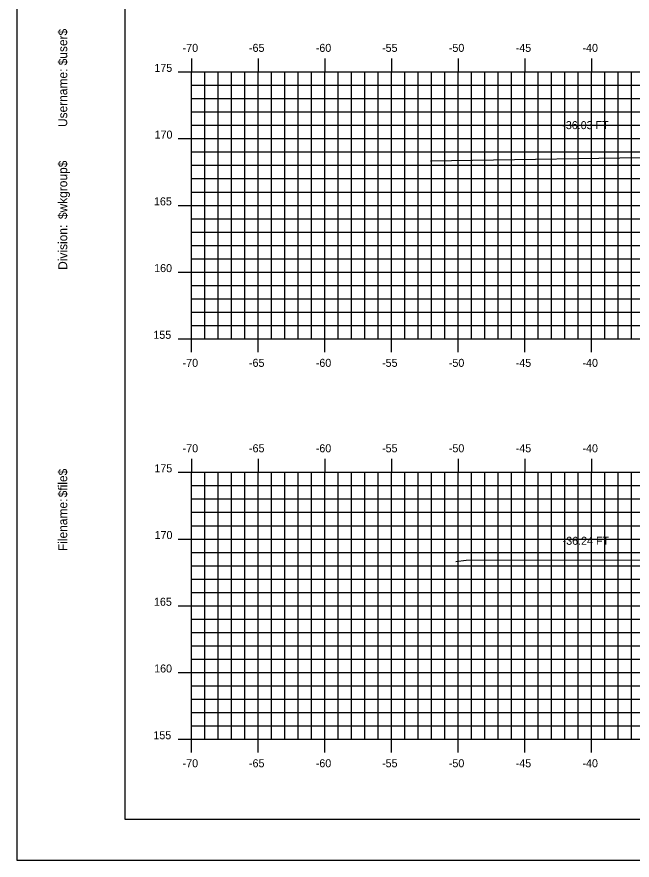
# Model space of a CAD drawing. Extents: x 1141868 to 1142038, y 608981 to 609091.
# Drawn here: x 1141867.7 to 1141913.8, y 608981.3 to 609044.5 of the extents above; entities that cross this region are included whole.
import ezdxf

# ---------------------------------------------------------------- set-up
doc = ezdxf.new("R2010")
doc.units = 0
for name, color, linetype in [('BORDER', 7, 'Continuous'), ('D_Text_Standard', 7, 'Continuous'), ('H_V ANNOTATION', 7, 'Continuous'), ('MAJOR', 7, 'Continuous'), ('MINOR', 7, 'Continuous'), ('PLOT BOUNDARY', 7, 'Continuous'), ('S_Roadway_Centerline', 7, 'Continuous')]:
    doc.layers.add(name, color=color, linetype=linetype)

msp = doc.modelspace()

# ---------------------------------------------------------------- linework, layer by layer
at = {"layer": 'BORDER'}
msp.add_lwpolyline([(1141875.784, 608984.335), (1142035.784, 608984.335), (1142035.784, 609089.335), (1141875.784, 609089.335)], close=True, dxfattribs=at)
at = {"layer": 'MAJOR'}
for p, q in [((1141880.784, 609041.337), (1141880.784, 609040.335)), ((1141885.784, 609041.337), (1141885.784, 609040.335)), ((1141890.784, 609041.337), (1141890.784, 609040.335)), ((1141895.784, 609041.337), (1141895.784, 609040.335)), ((1141900.784, 609041.337), (1141900.784, 609040.335)), ((1141905.784, 609041.337), (1141905.784, 609040.335)), ((1141910.784, 609041.337), (1141910.784, 609040.335)), ((1141879.782, 609040.335), (1141880.784, 609040.335)), ((1141880.784, 609040.335), (1142020.784, 609040.335)), ((1141880.784, 609020.335), (1141880.784, 609040.335)), ((1141880.784, 609020.335), (1141880.784, 609040.335)), ((1141880.784, 609040.335), (1142020.784, 609040.335)), ((1141885.784, 609020.335), (1141885.784, 609040.335)), ((1141890.784, 609020.335), (1141890.784, 609040.335)), ((1141895.784, 609020.335), (1141895.784, 609040.335)), ((1141900.784, 609020.335), (1141900.784, 609040.335)), ((1141905.784, 609020.335), (1141905.784, 609040.335)), ((1141910.784, 609020.335), (1141910.784, 609040.335)), ((1141879.782, 609035.335), (1141880.784, 609035.335)), ((1141880.784, 609035.335), (1142020.784, 609035.335)), ((1141879.782, 609030.335), (1141880.784, 609030.335)), ((1141880.784, 609030.335), (1142020.784, 609030.335)), ((1141879.782, 609025.335), (1141880.784, 609025.335)), ((1141880.784, 609025.335), (1142020.784, 609025.335)), ((1141879.782, 609020.335), (1141880.784, 609020.335)), ((1141880.784, 609020.335), (1142020.784, 609020.335)), ((1141880.784, 609020.335), (1142020.784, 609020.335)), ((1141880.784, 609019.333), (1141880.784, 609020.335)), ((1141885.784, 609019.333), (1141885.784, 609020.335)), ((1141890.784, 609019.333), (1141890.784, 609020.335)), ((1141895.784, 609019.333), (1141895.784, 609020.335)), ((1141900.784, 609019.333), (1141900.784, 609020.335)), ((1141905.784, 609019.333), (1141905.784, 609020.335)), ((1141910.784, 609019.333), (1141910.784, 609020.335)), ((1141880.784, 609011.337), (1141880.784, 609010.335)), ((1141885.784, 609011.337), (1141885.784, 609010.335)), ((1141890.784, 609011.337), (1141890.784, 609010.335)), ((1141895.784, 609011.337), (1141895.784, 609010.335)), ((1141900.784, 609011.337), (1141900.784, 609010.335)), ((1141905.784, 609011.337), (1141905.784, 609010.335)), ((1141910.784, 609011.337), (1141910.784, 609010.335)), ((1141879.782, 609010.335), (1141880.784, 609010.335)), ((1141880.784, 609010.335), (1142020.784, 609010.335)), ((1141880.784, 608990.335), (1141880.784, 609010.335)), ((1141880.784, 608990.335), (1141880.784, 609010.335)), ((1141880.784, 609010.335), (1142020.784, 609010.335)), ((1141885.784, 608990.335), (1141885.784, 609010.335)), ((1141890.784, 608990.335), (1141890.784, 609010.335)), ((1141895.784, 608990.335), (1141895.784, 609010.335)), ((1141900.784, 608990.335), (1141900.784, 609010.335)), ((1141905.784, 608990.335), (1141905.784, 609010.335)), ((1141910.784, 608990.335), (1141910.784, 609010.335)), ((1141879.782, 609005.335), (1141880.784, 609005.335)), ((1141880.784, 609005.335), (1142020.784, 609005.335)), ((1141879.782, 609000.335), (1141880.784, 609000.335)), ((1141880.784, 609000.335), (1142020.784, 609000.335)), ((1141879.782, 608995.335), (1141880.784, 608995.335)), ((1141880.784, 608995.335), (1142020.784, 608995.335)), ((1141879.782, 608990.335), (1141880.784, 608990.335)), ((1141880.784, 608990.335), (1142020.784, 608990.335)), ((1141880.784, 608990.335), (1142020.784, 608990.335)), ((1141880.784, 608989.333), (1141880.784, 608990.335)), ((1141885.784, 608989.333), (1141885.784, 608990.335)), ((1141890.784, 608989.333), (1141890.784, 608990.335)), ((1141895.784, 608989.333), (1141895.784, 608990.335)), ((1141900.784, 608989.333), (1141900.784, 608990.335)), ((1141905.784, 608989.333), (1141905.784, 608990.335)), ((1141910.784, 608989.333), (1141910.784, 608990.335))]:
    msp.add_line(p, q, dxfattribs=at)
at = {"layer": 'MINOR'}
for p, q in [((1141881.784, 609020.335), (1141881.784, 609040.335)), ((1141882.784, 609020.335), (1141882.784, 609040.335)), ((1141883.784, 609020.335), (1141883.784, 609040.335)), ((1141884.784, 609020.335), (1141884.784, 609040.335)), ((1141886.784, 609020.335), (1141886.784, 609040.335)), ((1141887.784, 609020.335), (1141887.784, 609040.335)), ((1141888.784, 609020.335), (1141888.784, 609040.335)), ((1141889.784, 609020.335), (1141889.784, 609040.335)), ((1141891.784, 609020.335), (1141891.784, 609040.335)), ((1141892.784, 609020.335), (1141892.784, 609040.335)), ((1141893.784, 609020.335), (1141893.784, 609040.335)), ((1141894.784, 609020.335), (1141894.784, 609040.335)), ((1141896.784, 609020.335), (1141896.784, 609040.335)), ((1141897.784, 609020.335), (1141897.784, 609040.335)), ((1141898.784, 609020.335), (1141898.784, 609040.335)), ((1141899.784, 609020.335), (1141899.784, 609040.335)), ((1141901.784, 609020.335), (1141901.784, 609040.335)), ((1141902.784, 609020.335), (1141902.784, 609040.335)), ((1141903.784, 609020.335), (1141903.784, 609040.335)), ((1141904.784, 609020.335), (1141904.784, 609040.335)), ((1141906.784, 609020.335), (1141906.784, 609040.335)), ((1141907.784, 609020.335), (1141907.784, 609040.335)), ((1141908.784, 609020.335), (1141908.784, 609040.335)), ((1141909.784, 609020.335), (1141909.784, 609040.335)), ((1141911.784, 609020.335), (1141911.784, 609040.335)), ((1141912.784, 609020.335), (1141912.784, 609040.335)), ((1141913.784, 609020.335), (1141913.784, 609040.335)), ((1141880.784, 609039.335), (1142020.784, 609039.335)), ((1141880.784, 609039.335), (1141881.786, 609039.335)), ((1141880.784, 609038.335), (1142020.784, 609038.335)), ((1141880.784, 609038.335), (1141881.786, 609038.335)), ((1141880.784, 609037.335), (1142020.784, 609037.335)), ((1141880.784, 609037.335), (1141881.786, 609037.335)), ((1141880.784, 609036.335), (1142020.784, 609036.335)), ((1141880.784, 609036.335), (1141881.786, 609036.335)), ((1141880.784, 609034.335), (1142020.784, 609034.335)), ((1141880.784, 609034.335), (1141881.786, 609034.335)), ((1141880.784, 609033.335), (1142020.784, 609033.335)), ((1141880.784, 609033.335), (1141881.786, 609033.335)), ((1141880.784, 609032.335), (1142020.784, 609032.335)), ((1141880.784, 609032.335), (1141881.786, 609032.335)), ((1141880.784, 609031.335), (1142020.784, 609031.335)), ((1141880.784, 609031.335), (1141881.786, 609031.335)), ((1141880.784, 609029.335), (1142020.784, 609029.335)), ((1141880.784, 609029.335), (1141881.786, 609029.335)), ((1141880.784, 609028.335), (1142020.784, 609028.335)), ((1141880.784, 609028.335), (1141881.786, 609028.335)), ((1141880.784, 609027.335), (1142020.784, 609027.335)), ((1141880.784, 609027.335), (1141881.786, 609027.335)), ((1141880.784, 609026.335), (1142020.784, 609026.335)), ((1141880.784, 609026.335), (1141881.786, 609026.335)), ((1141880.784, 609024.335), (1142020.784, 609024.335)), ((1141880.784, 609024.335), (1141881.786, 609024.335)), ((1141880.784, 609023.335), (1142020.784, 609023.335)), ((1141880.784, 609023.335), (1141881.786, 609023.335)), ((1141880.784, 609022.335), (1142020.784, 609022.335)), ((1141880.784, 609022.335), (1141881.786, 609022.335)), ((1141880.784, 609021.335), (1142020.784, 609021.335)), ((1141880.784, 609021.335), (1141881.786, 609021.335)), ((1141881.784, 608990.335), (1141881.784, 609010.335)), ((1141882.784, 608990.335), (1141882.784, 609010.335)), ((1141883.784, 608990.335), (1141883.784, 609010.335)), ((1141884.784, 608990.335), (1141884.784, 609010.335)), ((1141886.784, 608990.335), (1141886.784, 609010.335)), ((1141887.784, 608990.335), (1141887.784, 609010.335)), ((1141888.784, 608990.335), (1141888.784, 609010.335)), ((1141889.784, 608990.335), (1141889.784, 609010.335)), ((1141891.784, 608990.335), (1141891.784, 609010.335)), ((1141892.784, 608990.335), (1141892.784, 609010.335)), ((1141893.784, 608990.335), (1141893.784, 609010.335)), ((1141894.784, 608990.335), (1141894.784, 609010.335)), ((1141896.784, 608990.335), (1141896.784, 609010.335)), ((1141897.784, 608990.335), (1141897.784, 609010.335)), ((1141898.784, 608990.335), (1141898.784, 609010.335)), ((1141899.784, 608990.335), (1141899.784, 609010.335)), ((1141901.784, 608990.335), (1141901.784, 609010.335)), ((1141902.784, 608990.335), (1141902.784, 609010.335)), ((1141903.784, 608990.335), (1141903.784, 609010.335)), ((1141904.784, 608990.335), (1141904.784, 609010.335)), ((1141906.784, 608990.335), (1141906.784, 609010.335)), ((1141907.784, 608990.335), (1141907.784, 609010.335)), ((1141908.784, 608990.335), (1141908.784, 609010.335)), ((1141909.784, 608990.335), (1141909.784, 609010.335)), ((1141911.784, 608990.335), (1141911.784, 609010.335)), ((1141912.784, 608990.335), (1141912.784, 609010.335)), ((1141913.784, 608990.335), (1141913.784, 609010.335)), ((1141880.784, 609009.335), (1142020.784, 609009.335)), ((1141880.784, 609009.335), (1141881.786, 609009.335)), ((1141880.784, 609008.335), (1142020.784, 609008.335)), ((1141880.784, 609008.335), (1141881.786, 609008.335)), ((1141880.784, 609007.335), (1142020.784, 609007.335)), ((1141880.784, 609007.335), (1141881.786, 609007.335)), ((1141880.784, 609006.335), (1142020.784, 609006.335)), ((1141880.784, 609006.335), (1141881.786, 609006.335)), ((1141880.784, 609004.335), (1142020.784, 609004.335)), ((1141880.784, 609004.335), (1141881.786, 609004.335)), ((1141880.784, 609003.335), (1142020.784, 609003.335)), ((1141880.784, 609003.335), (1141881.786, 609003.335)), ((1141880.784, 609002.335), (1142020.784, 609002.335)), ((1141880.784, 609002.335), (1141881.786, 609002.335)), ((1141880.784, 609001.335), (1142020.784, 609001.335)), ((1141880.784, 609001.335), (1141881.786, 609001.335)), ((1141880.784, 608999.335), (1142020.784, 608999.335)), ((1141880.784, 608999.335), (1141881.786, 608999.335)), ((1141880.784, 608998.335), (1142020.784, 608998.335)), ((1141880.784, 608998.335), (1141881.786, 608998.335)), ((1141880.784, 608997.335), (1142020.784, 608997.335)), ((1141880.784, 608997.335), (1141881.786, 608997.335)), ((1141880.784, 608996.335), (1142020.784, 608996.335)), ((1141880.784, 608996.335), (1141881.786, 608996.335)), ((1141880.784, 608994.335), (1142020.784, 608994.335)), ((1141880.784, 608994.335), (1141881.786, 608994.335)), ((1141880.784, 608993.335), (1142020.784, 608993.335)), ((1141880.784, 608993.335), (1141881.786, 608993.335)), ((1141880.784, 608992.335), (1142020.784, 608992.335)), ((1141880.784, 608992.335), (1141881.786, 608992.335)), ((1141880.784, 608991.335), (1142020.784, 608991.335)), ((1141880.784, 608991.335), (1141881.786, 608991.335))]:
    msp.add_line(p, q, dxfattribs=at)
at = {"layer": 'PLOT BOUNDARY'}
msp.add_lwpolyline([(1141867.691, 608981.276), (1142037.691, 608981.276), (1142037.691, 609091.276), (1141867.691, 609091.276)], close=True, dxfattribs=at)
at = {"layer": 'S_Roadway_Centerline'}
for points in [[(1141898.714, 609033.675), (1141917.629, 609033.96), (1141928.482, 609033.842), (1141932.036, 609032.906), (1141933.204, 609032.648), (1141934.418, 609032.95), (1141936.171, 609033.793), (1141938.888, 609033.718), (1141940.258, 609033.785), (1141943.4, 609033.889), (1141951.951, 609034.107), (1141958.412, 609033.998), (1141962.656, 609033.973), (1141964.386, 609033.91), (1141966.817, 609033.803), (1141966.877, 609033.693), (1141968.111, 609033.369), (1141969.228, 609033.74), (1141970.594, 609033.351), (1141971.805, 609033.711), (1141975.428, 609033.517), (1141988.146, 609032.877), (1141997.951, 609033.132)], [(1141900.602, 609003.644), (1141901.394, 609003.749), (1141915.746, 609003.783), (1141928.977, 609003.95), (1141931.483, 609003.382), (1141934.466, 609002.656), (1141935.906, 609003.083), (1141937.139, 609003.558), (1141939.061, 609003.555), (1141941.092, 609003.71), (1141946.4, 609003.848), (1141952.444, 609004.051), (1141957.538, 609004.023), (1141963.377, 609003.905), (1141965.582, 609003.828), (1141967.5, 609003.599), (1141969.235, 609003.105), (1141970.695, 609002.835), (1141974.484, 609003.124), (1141975.978, 609003.567), (1141986.319, 609003.2), (1141995.084, 609003.033)]]:
    msp.add_lwpolyline(points, dxfattribs=at)

# ---------------------------------------------------------------- texts
at = {"layer": 'BORDER'}
for s, p in [('$user$', (1141871.469, 609040.827)), ('Username:', (1141871.469, 609036.203)), ('$wkgroup$', (1141871.469, 609029.305)), ('Division:', (1141871.469, 609025.501)), ('$file$', (1141871.469, 609008.461)), ('Filename:', (1141871.469, 609004.433))]:
    msp.add_text(s, height=0.6696, rotation=90, dxfattribs=at).set_placement(p)
at = {"layer": 'D_Text_Standard'}
for s, p in [('-36.03 FT', (1141908.594, 609036.046)), ('-36.24 FT', (1141908.621, 609004.903))]:
    msp.add_text(s, height=0.6, dxfattribs=at).set_placement(p)
at = {"layer": 'H_V ANNOTATION'}
for s, p in [('-70', (1141880.125, 609041.835)), ('-65', (1141885.101, 609041.835)), ('-60', (1141890.109, 609041.835)), ('-55', (1141895.08, 609041.835)), ('-50', (1141900.088, 609041.835)), ('-45', (1141905.101, 609041.835)), ('-40', (1141910.109, 609041.835)), ('175', (1141878.005, 609040.335)), ('170', (1141878.021, 609035.335)), ('165', (1141877.973, 609030.335)), ('160', (1141877.989, 609025.335)), ('155', (1141877.93, 609020.335)), ('-70', (1141880.125, 609018.235)), ('-65', (1141885.101, 609018.235)), ('-60', (1141890.109, 609018.235)), ('-55', (1141895.08, 609018.235)), ('-50', (1141900.088, 609018.235)), ('-45', (1141905.101, 609018.235)), ('-40', (1141910.109, 609018.235)), ('-70', (1141880.125, 609011.835)), ('-65', (1141885.101, 609011.835)), ('-60', (1141890.109, 609011.835)), ('-55', (1141895.08, 609011.835)), ('-50', (1141900.088, 609011.835)), ('-45', (1141905.101, 609011.835)), ('-40', (1141910.109, 609011.835)), ('175', (1141878.005, 609010.335)), ('170', (1141878.021, 609005.335)), ('165', (1141877.973, 609000.335)), ('160', (1141877.989, 608995.335)), ('155', (1141877.93, 608990.335)), ('-70', (1141880.125, 608988.235)), ('-65', (1141885.101, 608988.235)), ('-60', (1141890.109, 608988.235)), ('-55', (1141895.08, 608988.235)), ('-50', (1141900.088, 608988.235)), ('-45', (1141905.101, 608988.235)), ('-40', (1141910.109, 608988.235))]:
    msp.add_text(s, height=0.6, dxfattribs=at).set_placement(p)
at = {"layer": 'MAJOR'}
for p in [(1141880.779, 609020.335), (1141880.779, 608990.335)]:
    msp.add_text('-', height=0.006, dxfattribs=at).set_placement(p)

doc.saveas('drawing.dxf')
